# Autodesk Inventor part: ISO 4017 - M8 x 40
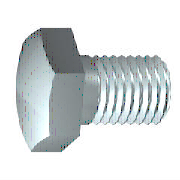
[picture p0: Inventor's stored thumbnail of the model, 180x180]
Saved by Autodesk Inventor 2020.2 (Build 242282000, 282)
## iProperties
Manager: www.cadconsulting.pl
Company: Fabian Stasiak CAD Consulting
Created: 2011-02
Part Number: ISO 4017 - M8 x 40
Material: Stal nierdzewna, 440C
Description: Wkręty z łbem sześciokątnym
Document SubType Name: Modeling
Standard: ISO 4017
Designer: F.Stasiak
Standard Revision: Third edition 1999-08-15
Standards Organization: ISO
Language: pl-PL
Size Designation: M8 x 40
Categories: <MemberInstance><Categories><Category DisplayName="Mocowania" InternalName="e4da775c-781d-43d5-af7c-5136215cf5a6" Mnemonic="FSTN"><Category DisplayName="Śruby"
Density: 7.75 g/cm^3
Appearance: Metal-Stal
IsCustomPart: 0
Author: F.Stasiak
Subject: Zbiór ćwiczeń. Autodesk Inventor 2020. Kurs podstawowy
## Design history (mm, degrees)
sketch "Szkic1"
  geometry: L1 (0, 5.815)-(0, 4); L2 (4, 4)-(40, 4); L3 (40, 4)-(40, 0); L4 (40, 0)-(-0.6, 0); L5 (-8.72, 0)-(48.12, 0) reference; L6 (-0.6, 0)-(-0.6, 5.815); L7 (-0.6, 5.815)-(0, 5.815); L8 (4, 4)-(3.233, 4); L9 (3.233, 4)-(0, 4); L10 (0, -1.163)-(0, 6.978) reference
  constraints: 16 end point, 2 collinear, 2 perpendicular, 1 parallel
  dimensions: "d0" = 40 distance between parallel lines of L3 L1 (= NLG); "d1" = 36 distance from line of L2.start L3 (= GEL); "d2" = 8 diameter of L2 L4 (= GD); "d9" = 0.6001 distance between parallel lines of L6 L1 (computed from SD); "d10" = 11.63 diameter of L7 L4 (= SD2); "d13" = 0.76691 distance of L2.start L8.end (computed from GAL); "d14" = 8 diameter of L9 L4 (= BDM)
revolve "Bryła" sketch "Szkic1" stored, may be unused: angle "d12" = 90 deg
sketch "Szkic2"
  geometry: L1 (0, 7.506)-(6.5, 3.753); L2 (6.5, 3.753)-(6.5, -3.753); L3 (6.5, -3.753)-(0, -7.506); L4 (0, -7.506)-(-6.5, -3.753); L5 (-6.5, -3.753)-(-6.5, 3.753); L6 (-6.5, 3.753)-(0, 7.506); 2 further points
  constraints: 12 end point, 1 coincident, 1 vertical, 11 other
  dimensions: "d11" = 13 distance between parallel lines of L5 L2 (= SW)
extrude "Głowica" join sketch "Szkic2" distance "d3" = 4.7 (= KOH - SD); taper "d4" = 0 deg
sketch "Szkic4"
  geometry: L1 (-5.3, 6.5)-(-5.3, 7.506); L2 (-5.3, 7.506)-(-4.72, 7.506); L3 (-4.72, 7.506)-(-5.3, 6.5); L4 (-6.24, 0)-(0.34, 0) reference; L5 (-0.6, 7.506)-(-5.3, 7.506) reference; L6 (-5.3, 3.753)-(-5.3, 7.506) reference
  constraints: 6 end point, 2 collinear, 1 perpendicular, 1 vertical
  dimensions: "d5" = 30 deg angle of L3 L1 (= ANG1); "d19" = 13 diameter of L1.start L4 (= SW0)
revolve "Faza1" sketch "Szkic4" stored, may be unused: angle "d21" = 90 deg
workplane "Work Plane1"
body "Solid1"
feature "Gwint" dims "d15" = 36 (= GEL), "d16" = 0
chamfer "Faza2" distance "d6" = 0.76681 (= -0.5 x SPD + 0.5 x GD); stored, may be unused: second distance "d7" = 0.76691 (computed from GUL), angle "d55" = 45 deg
other parameters: "NLG" = 40 [user parameter; used in 1 equation term], "GD" = 8 (= NND) [user parameter; used in 2 equation terms], "BDM" = 8 (= NND) [user parameter; used in 1 equation term], "KOH" = 5.3 [user parameter; used in 1 equation term], "GEL" = 36 [user parameter; used in 2 equation terms], "SW" = 13 [user parameter; used in 2 equation terms], "SW0" = 13 (= SW) [user parameter; used in 1 equation term], "SPD" = 6.46637 (= NND - 1.2269 x PTC) [user parameter; used in 1 equation term], "SD2" = 11.63 [user parameter; used in 2 equation terms], "SD" = 0.6 [user parameter; used in 2 equation terms], "ANG1" = 30 deg [user parameter; used in 1 equation term], "GAL" = 0.76681 (= 0.61345 x PTC) [user parameter; used in 1 equation term], "GUL" = 0.76681 (= 0.61345 x PTC) [user parameter; used in 1 equation term], "d8" = 0, "RR" = 0.4 [user parameter], "d57" = 0, "d58" = 0, "TPU" = 8 (computed from PTC) [user parameter], "GD1" = 6.46637 (= THREADDIA - 1.2269 x PTC) [user parameter], "THREADDIA" = 8 [user parameter; used in 1 equation term], "SDH" = 11.63 (= SD2) [user parameter], "SDHG" = 4 [user parameter], "TOA" = 30 deg [user parameter], "PTC" = 1.25 [user parameter; used in 5 equation terms], "NND" = 8 [user parameter; used in 3 equation terms], "E0" = 15.015 [user parameter]
